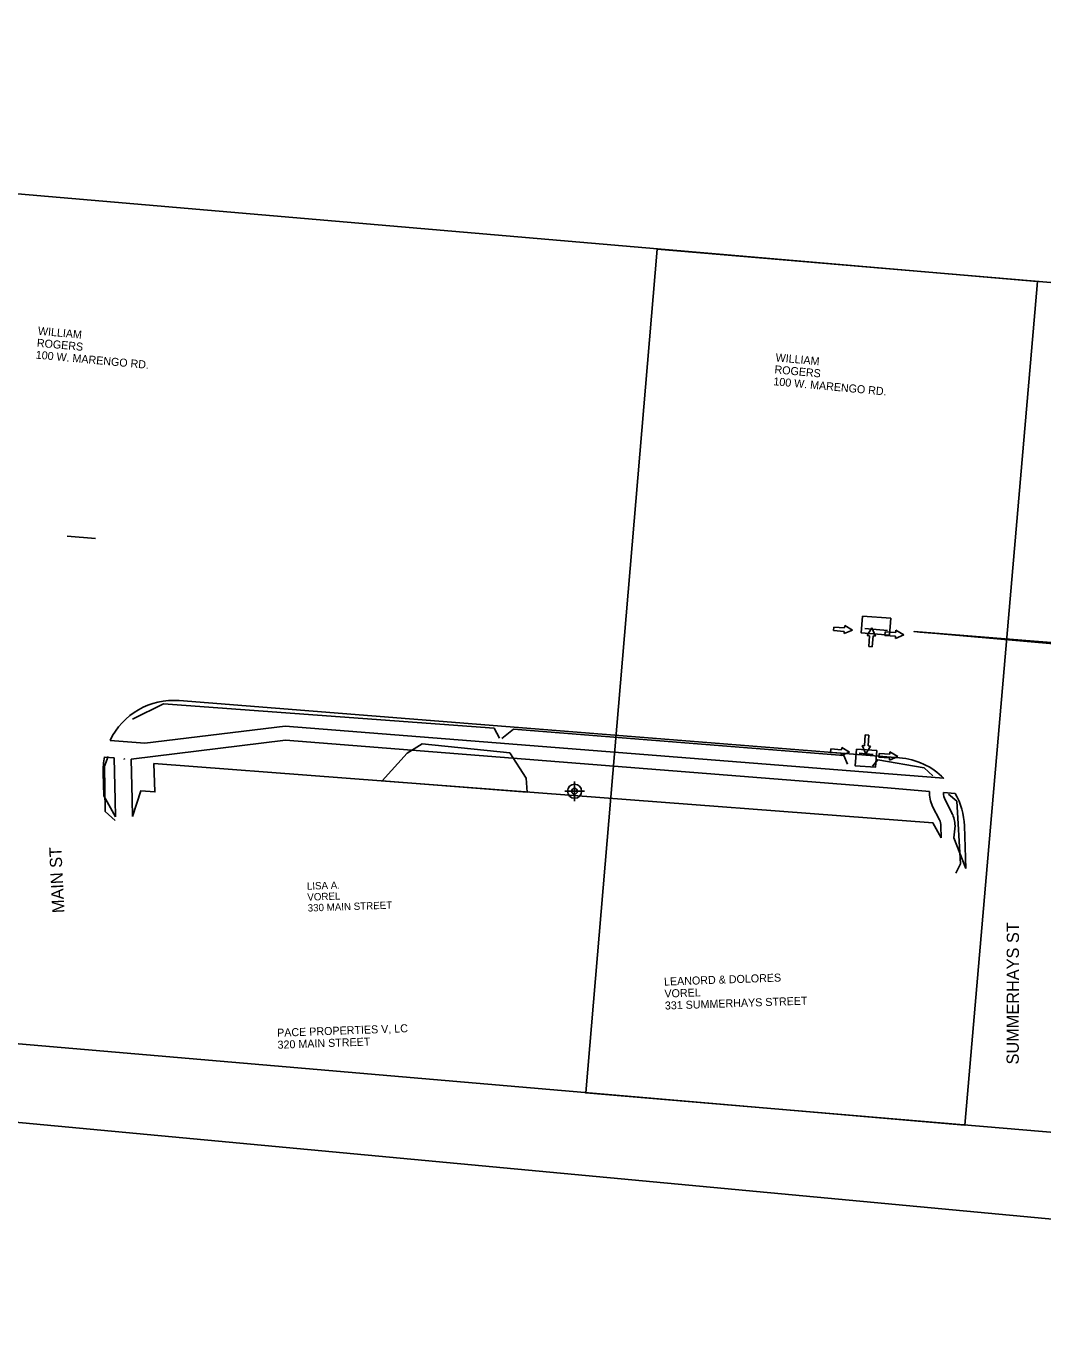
# Model space of a CAD drawing. Extents: x 20499351 to 20505779, y 7953198 to 7954637.
# Drawn here: x 20500937.9 to 20501297.9, y 7953706.6 to 7954174 of the extents above; entities that cross this region are included whole.
import ezdxf

# ---------------------------------------------------------------- set-up
doc = ezdxf.new("R2010")
doc.units = 0
for name, color, linetype in [('_CIVIL_CONSTRUCTION', 7, 'Continuous'), ('Contours Major', 7, 'Continuous'), ('Contours Minor', 7, 'Continuous'), ('Mulch', 7, 'Continuous'), ('NamedBoundary', 7, 'Continuous'), ('Terrain', 7, 'Continuous'), ('Terrains (working)', 7, 'Continuous'), ('TL_GroundIntercept', 7, 'Continuous')]:
    doc.layers.add(name, color=color, linetype=linetype)

msp = doc.modelspace()

# ---------------------------------------------------------------- linework, layer by layer
at = {"layer": '_CIVIL_CONSTRUCTION'}
for p, q in [((20501223.81, 7953959.88), (20501223.89, 7953961.15)), ((20501223.89, 7953961.15), (20501227.7, 7953960.88)), ((20501227.7, 7953960.88), (20501227.76, 7953961.67)), ((20501227.76, 7953961.67), (20501230.51, 7953960.04)), ((20501235.75, 7953958.15), (20501237.4, 7953960.9)), ((20501237.4, 7953960.9), (20501238.61, 7953957.94)), ((20501227.61, 7953959.61), (20501223.81, 7953959.88)), ((20501230.51, 7953960.04), (20501227.56, 7953958.82)), ((20501227.56, 7953958.82), (20501227.61, 7953959.61)), ((20501236.55, 7953958.09), (20501235.75, 7953958.15)), ((20501236.26, 7953954.29), (20501236.55, 7953958.09)), ((20501237.81, 7953958), (20501237.53, 7953954.19)), ((20501238.61, 7953957.94), (20501237.81, 7953958)), ((20501241.94, 7953958.19), (20501242.03, 7953959.46)), ((20501245.75, 7953957.93), (20501241.94, 7953958.19)), ((20501242.03, 7953959.46), (20501245.84, 7953959.2)), ((20501248.65, 7953958.38), (20501245.7, 7953957.14)), ((20501245.7, 7953957.14), (20501245.75, 7953957.93)), ((20501245.84, 7953959.2), (20501245.89, 7953960)), ((20501245.89, 7953960), (20501248.65, 7953958.38)), ((20501237.53, 7953954.19), (20501236.26, 7953954.29)), ((20501234.79, 7953919.11), (20501235.06, 7953922.92)), ((20501235.06, 7953922.92), (20501236.33, 7953922.83)), ((20501236.33, 7953922.83), (20501236.06, 7953919.02)), ((20501222.72, 7953916.75), (20501222.83, 7953918.02)), ((20501222.83, 7953918.02), (20501226.63, 7953917.69)), ((20501226.63, 7953917.69), (20501226.7, 7953918.48)), ((20501226.7, 7953918.48), (20501229.43, 7953916.8)), ((20501235.22, 7953916.21), (20501233.99, 7953919.17)), ((20501233.99, 7953919.17), (20501234.79, 7953919.11)), ((20501236.85, 7953918.97), (20501235.22, 7953916.21)), ((20501236.06, 7953919.02), (20501236.85, 7953918.97)), ((20501226.52, 7953916.42), (20501222.72, 7953916.75)), ((20501229.43, 7953916.8), (20501226.45, 7953915.63)), ((20501226.45, 7953915.63), (20501226.52, 7953916.42)), ((20501239.85, 7953915.06), (20501239.93, 7953916.33)), ((20501243.66, 7953914.83), (20501239.85, 7953915.06)), ((20501239.93, 7953916.33), (20501243.74, 7953916.1)), ((20501246.56, 7953915.29), (20501243.62, 7953914.03)), ((20501243.62, 7953914.03), (20501243.66, 7953914.83)), ((20501243.74, 7953916.1), (20501243.79, 7953916.89)), ((20501243.79, 7953916.89), (20501246.56, 7953915.29))]:
    msp.add_line(p, q, dxfattribs=at)
at = {"layer": 'Contours Major'}
for p, q in [((20500952.3, 7953993.35), (20500962.39, 7953992.58)), ((20500992.06, 7953935.1), (20501247.15, 7953914.83)), ((20501029.61, 7953926.09), (20500979.91, 7953919.99)), ((20501243.26, 7953909.12), (20501029.61, 7953926.09)), ((20500979.91, 7953919.99), (20500967.53, 7953920.97)), ((20501029.72, 7953921.07), (20500975.06, 7953914.36)), ((20501242.86, 7953904.13), (20501029.72, 7953921.07)), ((20500965.57, 7953915.11), (20500969.05, 7953914.83)), ((20500969.05, 7953914.83), (20500969.36, 7953899.86)), ((20500975.06, 7953914.36), (20500975.36, 7953900.02)), ((20500965.3, 7953901.35), (20500965.08, 7953909.52)), ((20501262.87, 7953907.56), (20501243.26, 7953909.12)), ((20501257.81, 7953902.94), (20501242.86, 7953904.13)), ((20500969.49, 7953893.86), (20500965.3, 7953901.35)), ((20500969.36, 7953899.86), (20500969.49, 7953893.86)), ((20500975.36, 7953900.02), (20500975.54, 7953894.02)), ((20501266.92, 7953902.22), (20501262.8, 7953902.55)), ((20501263.33, 7953899.88), (20501265.76, 7953895.12)), ((20501261.3, 7953892.85), (20501258.87, 7953897.61)), ((20501261.93, 7953886.46), (20501261.85, 7953890.68)), ((20501266.85, 7953890.77), (20501266.35, 7953886.51)), ((20501270.66, 7953875.56), (20501270.15, 7953890.74)), ((20501266.35, 7953886.51), (20501270.66, 7953875.56))]:
    msp.add_line(p, q, dxfattribs=at)
msp.add_lwpolyline([(20500975.54, 7953894.02), (20500978.41, 7953903.1), (20500983.42, 7953902.72), (20500983.07, 7953912.78), (20501119.32, 7953902.4), (20501258.97, 7953891.76), (20501261.93, 7953886.46)], dxfattribs=at)
for centre, radius, start, end in [((20500990.08, 7953910.18), 25, 85.4564, 154.4103), ((20500990.08, 7953910.18), 25, 168.6151, 181.51), ((20501245.17, 7953889.9), 25, 44.9206, 85.4564), ((20501267.78, 7953902.15), 10, 175.4564, 207.0356), ((20501267.78, 7953902.15), 5, 175.4564, 207.0356), ((20501245.17, 7953889.9), 25, 1.9056, 29.5122), ((20501256.85, 7953890.58), 10, 1.1255, 27.0356), ((20501256.85, 7953890.58), 5, 1.1255, 27.0356)]:
    msp.add_arc(centre, radius, start, end, dxfattribs=at)
at = {"layer": 'Contours Minor'}
for p, q in [((20501242.92, 7953959.93), (20501234.94, 7953960.59)), ((20501252.3, 7953959.56), (20501318.31, 7953953.75)), ((20501458.95, 7953943.14), (20501254.33, 7953959.4)), ((20500972.54, 7953914.56), (20500972.68, 7953914.27)), ((20501232.89, 7953916.43), (20501237.88, 7953916.04))]:
    msp.add_line(p, q, dxfattribs=at)
for points in [[(20501234.02, 7953965.07), (20501233.54, 7953959.11), (20501243.62, 7953958.32), (20501244.09, 7953964.27)], [(20501231.89, 7953917.93), (20501239.11, 7953917.36), (20501238.65, 7953911.46), (20501231.42, 7953912.04)]]:
    msp.add_lwpolyline(points, close=True, dxfattribs=at)
for points in [[(20501254.33, 7953959.4), (20501254.33, 7953959.4), (20501252.3, 7953959.56), (20501252.3, 7953959.56)], [(20501105.46, 7953921.73), (20501103.56, 7953925.38), (20500986.46, 7953933.93), (20500975.45, 7953928.48)], [(20501228.72, 7953912.6), (20501227.46, 7953915.62), (20501110.43, 7953925.01), (20501106.25, 7953921.65)], [(20500966.9, 7953915.28), (20500965.56, 7953911.87), (20500965.75, 7953895.85), (20500969.34, 7953892.62)], [(20501237.63, 7953911.82), (20501239.48, 7953914.11), (20501255.85, 7953911.28), (20501258.92, 7953908.41)], [(20501264.47, 7953901.99), (20501267.46, 7953899.44), (20501268.77, 7953877.24), (20501267.11, 7953874)]]:
    msp.add_lwpolyline(points, dxfattribs=at)
at = {"layer": 'Mulch'}
msp.add_lwpolyline([(20501318.33, 7953954.31), (20501252.3, 7953959.56), (20501318.31, 7953953.75)], close=True, dxfattribs=at)
at = {"layer": 'NamedBoundary'}
for points in [[(20500359.01, 7954164.14), (20500333.3, 7953865.25), (20501270.32, 7953784.65), (20501296.03, 7954083.54)], [(20501161.33, 7954095.04), (20501136.01, 7953796.11), (20502073.14, 7953716.74), (20502098.46, 7954015.67)]]:
    msp.add_lwpolyline(points, close=True, dxfattribs=at)
at = {"layer": 'Terrain'}
msp.add_lwpolyline([(20501791.06, 7953833.84), (20501779.66, 7953706.56), (20499351.13, 7953933.78), (20499411.85, 7954636.65), (20501855.07, 7954405.25), (20501814.1, 7954091.19), (20501791.1, 7953834.34)], dxfattribs=at)
at = {"layer": 'Terrains (working)'}
for p, q in [((20501132.08, 7953906.48), (20501132.08, 7953899.48)), ((20501128.58, 7953902.98), (20501135.58, 7953902.98))]:
    msp.add_line(p, q, dxfattribs=at)
msp.add_lwpolyline([(20501063.79, 7953906.63), (20501115.27, 7953902.71), (20501114.92, 7953907.56), (20501109.1, 7953916.62), (20501078.11, 7953919.78), (20501072.78, 7953916.44), (20501063.91, 7953906.62)], dxfattribs=at)
for radius in [2.5, 1]:
    msp.add_circle((20501132.08, 7953902.98), radius, dxfattribs=at)

# ---------------------------------------------------------------- texts
at = {"layer": 'TL_GroundIntercept'}
for s, height, rotation, p in [('WILLIAM', 2.835, 354.7645, (20500941.9, 7954064.75)), ('ROGERS', 2.835, 354.7645, (20500941.51, 7954060.51)), ('100 W. MARENGO RD.', 2.8346, 354.7645, (20500941.12, 7954056.28)), ('ROGERS', 2.835, 354.7645, (20501202.79, 7954051.08)), ('WILLIAM', 2.835, 354.7645, (20501203.18, 7954055.32)), ('100 W. MARENGO RD.', 2.8346, 354.7645, (20501202.4, 7954046.85)), ('MAIN ST', 4.32, 92.8029, (20500951.41, 7953859.92)), ('VOREL', 2.58, 2.0248, (20501037.45, 7953864.2)), ('LISA A. ', 2.58, 2.0248, (20501037.31, 7953868.07)), ('330 MAIN STREET', 2.5802, 2.0248, (20501037.59, 7953860.33)), ('SUMMERHAYS ST', 4.32, 89.9003, (20501289.4, 7953806.17)), ('LEANORD & DOLORES', 2.8346, 2.0248, (20501163.8, 7953834.11)), ('VOREL', 2.835, 2.0248, (20501163.95, 7953829.86)), ('331 SUMMERHAYS STREET', 2.8346, 2.0248, (20501164.1, 7953825.61)), ('PACE PROPERTIES V, LC', 2.8346, 2.0248, (20501026.77, 7953815.98)), ('320 MAIN STREET', 2.8346, 2.0248, (20501026.92, 7953811.73))]:
    msp.add_text(s, height=height, rotation=rotation, dxfattribs=at).set_placement(p)

doc.saveas('drawing.dxf')
